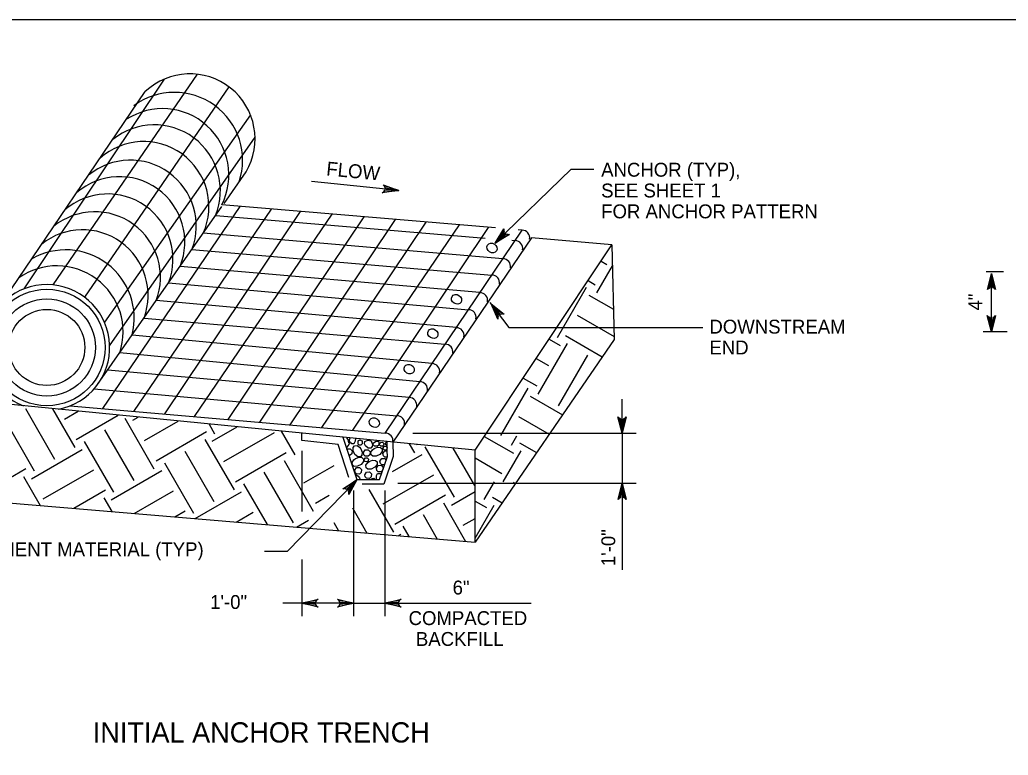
# Model space of a CAD drawing. Extents: x 636462 to 638208, y 299350 to 300538.
# Drawn here: x 636572.1 to 636785.5, y 299770.7 to 299929.4 of the extents above; entities that cross this region are included whole.
import ezdxf

# ---------------------------------------------------------------- set-up
doc = ezdxf.new("R2010")
doc.units = 0
doc.layers.add('1', color=7, linetype='Continuous')
doc.layers.add('Default', color=7, linetype='Continuous')

msp = doc.modelspace()

# ---------------------------------------------------------------- linework, layer by layer
at = {"layer": '1'}
for points in [[(637287.91, 299365.45), (637287.91, 299929.45), (636501.91, 299929.45), (636501.91, 299365.45), (637287.91, 299365.45), (637287.91, 299391.81), (637087.91, 299391.81), (637087.91, 299456.49), (637287.91, 299456.49), (637287.91, 299485.45), (637087.91, 299485.45), (637087.91, 299365.45), (637166.72, 299365.45), (637166.72, 299391.81), (637166.72, 299365.45), (637243.72, 299365.45), (637243.72, 299391.81), (637243.72, 299379.49), (637287.91, 299379.49)], [(636643.12, 299838.14), (636642.92, 299838.83), (636642.68, 299839.2)], [(636643.56, 299838.1), (636643.14, 299838.52), (636643.39, 299839.15)], [(636644.32, 299838.07), (636644.52, 299838.51), (636644.6, 299839.06)], [(636645.09, 299838.02), (636645.09, 299838.51), (636645.41, 299838.73), (636646, 299838.57), (636645.95, 299837.88)], [(636646.45, 299837.87), (636646.54, 299838.42), (636647.23, 299838.69), (636647.91, 299838.54), (636648.2, 299837.73)], [(636648.37, 299837.73), (636648.4, 299838.14), (636649.01, 299838.46), (636649.55, 299838.41), (636649.56, 299837.65)], [(636651.32, 299837.54), (636650.92, 299837.82), (636651.24, 299838.39)]]:
    msp.add_lwpolyline(points, dxfattribs=at)
at = {"layer": 'Default'}
for p, q in [((636573.01, 299871.38), (636603.28, 299916.64)), ((636610.34, 299917.69), (636579.2, 299872.22)), ((636565.66, 299864.62), (636599.16, 299913.93)), ((636586.08, 299869.54), (636617.24, 299914.97)), ((636621.87, 299908.92), (636590.32, 299864.17)), ((636591.46, 299859.08), (636622.86, 299904.07)), ((636674.6, 299881.18), (636691.11, 299897.18)), ((636691.11, 299897.18), (636696.01, 299897.18)), ((636616.15, 299889.76), (636620.94, 299896.61)), ((636588.84, 299850.67), (636615.69, 299889.11)), ((636619.6, 299889.16), (636589.91, 299845.49)), ((636596.71, 299844.9), (636626.4, 299888.58)), ((636674.8, 299884.5), (636615.65, 299889.49)), ((636632.56, 299888.06), (636603.31, 299844.33)), ((636609.77, 299843.77), (636639.48, 299887.48)), ((636614.35, 299887.18), (636672.52, 299882.31)), ((636646.35, 299886.9), (636616.96, 299843.15)), ((636623.88, 299842.55), (636653.15, 299886.32)), ((636659.73, 299885.77), (636630.34, 299842)), ((636637.28, 299841.4), (636667, 299885.15)), ((636673.16, 299884.63), (636643.86, 299840.83)), ((636650.96, 299840.21), (636680.51, 299884.01)), ((636680.51, 299884.01), (636679.68, 299884.08)), ((636676.35, 299877.85), (636611.68, 299883.36)), ((636682.57, 299882.35), (636652.59, 299838.25)), ((636678.28, 299881.83), (636678.99, 299881.77)), ((636699.89, 299880.82), (636682.57, 299882.35)), ((636609.23, 299879.86), (636673.97, 299874.33)), ((636671.41, 299870.53), (636606.65, 299876.17)), ((636696.61, 299870.48), (636700, 299876.35)), ((636697.55, 299877.33), (636698.8, 299876.61)), ((636784.44, 299875.01), (636780.69, 299875.01)), ((636604.18, 299872.62), (636668.92, 299866.84)), ((636688.12, 299860.82), (636694.43, 299871.74)), ((636694.75, 299873.12), (636696.27, 299872.24)), ((636694.89, 299870.02), (636700.23, 299866.94)), ((636666.32, 299862.98), (636601.51, 299868.8)), ((636673.55, 299868.43), (636677.68, 299863.01)), ((636598.88, 299865.04), (636663.9, 299859.4)), ((636692.37, 299865.65), (636700.38, 299861.03)), ((636677.68, 299863.01), (636719.56, 299863.01)), ((636661.07, 299855.2), (636596.33, 299861.38)), ((636686.34, 299860.51), (636688.71, 299859.14)), ((636689.85, 299861.28), (636697.81, 299856.68)), ((636785.26, 299862.1), (636780.03, 299862.1)), ((636684, 299848.64), (636690.31, 299859.56)), ((636658.43, 299851.29), (636593.65, 299857.56)), ((636683.54, 299856.3), (636686.19, 299854.77)), ((636688.37, 299846.12), (636694.67, 299857.04)), ((636656.13, 299847.87), (636591.04, 299853.82)), ((636680.74, 299852.1), (636683.67, 299850.4)), ((636588.11, 299849.75), (636653.49, 299843.96)), ((636675.91, 299839.67), (636681.82, 299849.91)), ((636682.28, 299848.18), (636689.23, 299844.17)), ((636573.26, 299845.49), (636579.56, 299834.58)), ((636579.1, 299845.46), (636583.93, 299837.1)), ((636582.93, 299846.09), (636650.96, 299840.21)), ((636581.74, 299843.22), (636584.69, 299844.92)), ((636584.26, 299838.85), (636593.31, 299844.07)), ((636594.72, 299843.43), (636601.03, 299832.51)), ((636596.44, 299842.97), (636597.62, 299843.65)), ((636679.76, 299843.81), (636686.37, 299840)), ((636568.89, 299842.97), (636575.19, 299832.05)), ((636598.97, 299838.6), (636606.24, 299842.8)), ((636612.93, 299842.14), (636614.13, 299840.08)), ((636613.62, 299838.43), (636619.02, 299841.55)), ((636590.35, 299840.91), (636596.66, 299829.99)), ((636601.49, 299834.24), (636612.4, 299840.54)), ((636616.14, 299834.06), (636627.06, 299840.37)), ((636628.48, 299840.62), (636631.43, 299835.51)), ((636632.96, 299838.63), (636632.94, 299840.18)), ((636641.8, 299839.31), (636644.85, 299830.17)), ((636656.92, 299840.21), (636705.14, 299840.21)), ((636672.34, 299839.5), (636678.67, 299835.85)), ((636678.21, 299837.57), (636679.4, 299839.63)), ((636585.99, 299838.39), (636592.29, 299827.47)), ((636612.03, 299838.86), (636618.33, 299827.94)), ((636640.81, 299837.71), (636632.96, 299838.63)), ((636643.08, 299830.64), (636640.81, 299837.71)), ((636651.41, 299836.41), (636651.35, 299838.34)), ((636652.59, 299838.25), (636652.69, 299835.14)), ((636656.15, 299837.9), (636657.26, 299835.97)), ((636657.72, 299837.69), (636657.81, 299837.74)), ((636659.53, 299837.27), (636665.83, 299826.35)), ((636665.52, 299836.98), (636670.2, 299828.88)), ((636679.98, 299838.11), (636683.63, 299836.01)), ((636574.61, 299830.36), (636585.52, 299836.66)), ((636607.66, 299836.34), (636613.96, 299825.42)), ((636618.66, 299829.69), (636629.58, 299836)), ((636632.96, 299836.35), (636632.96, 299823.3)), ((636649.71, 299830.17), (636651.44, 299835.15)), ((636652.69, 299835.14), (636650.68, 299829.15)), ((636651.44, 299835.15), (636651.41, 299836.4)), ((636652.55, 299831.89), (636658.94, 299835.58)), ((636670.34, 299834.83), (636676.15, 299831.48)), ((636676.45, 299829.65), (636680.32, 299836.35)), ((636603.29, 299833.82), (636609.59, 299822.9)), ((636629.12, 299834.28), (636635.43, 299823.36)), ((636633.37, 299829.45), (636639.92, 299833.23)), ((636562.43, 299826.24), (636573.35, 299832.54)), ((636572.89, 299830.82), (636576.49, 299824.58)), ((636577.13, 299826), (636588.05, 299832.3)), ((636591.78, 299825.82), (636602.7, 299832.13)), ((636624.75, 299831.75), (636631.06, 299820.84)), ((636650.54, 299824.91), (636661.46, 299831.21)), ((636620.39, 299829.23), (636625.47, 299820.44)), ((636644.88, 299830.1), (636629.76, 299814.62)), ((636644.85, 299830.17), (636649.71, 299830.17)), ((636650.68, 299829.15), (636645.99, 299829.2)), ((636653.7, 299829.39), (636705.14, 299829.39)), ((636672.34, 299825.84), (636674.55, 299829.66)), ((636678.55, 299829.64), (636679.06, 299829.35)), ((636583.7, 299823.97), (636590.57, 299827.93)), ((636590.19, 299826.26), (636591.91, 299823.27)), ((636596.75, 299822.86), (636605.23, 299827.76)), ((636609.95, 299821.75), (636619.93, 299827.51)), ((636635.89, 299825.08), (636638.85, 299826.79)), ((636644.14, 299827.78), (636644.14, 299800.69)), ((636647.41, 299828.01), (636652.73, 299818.79)), ((636650.85, 299827.78), (636650.85, 299800.69)), ((636653.06, 299820.54), (636663.98, 299826.85)), ((636665.24, 299824.66), (636670.34, 299827.61)), ((636674.11, 299826.38), (636676.2, 299825.17)), ((636663.52, 299825.12), (636668.32, 299816.82)), ((636670.34, 299825.53), (636672.81, 299824.11)), ((636670.34, 299817.51), (636674.45, 299824.62)), ((636605.55, 299822.12), (636607.75, 299823.39)), ((636618.74, 299821.01), (636622.45, 299823.14)), ((636643.86, 299824.06), (636647.01, 299818.62)), ((636659.16, 299822.6), (636662.2, 299817.33)), ((636631.79, 299819.9), (636634.36, 299821.39)), ((636639.88, 299820.88), (636640.88, 299819.14)), ((636654.79, 299820.08), (636656.07, 299817.85)), ((636667.77, 299820.3), (636670.34, 299821.79)), ((636653.78, 299818.05), (636654.33, 299818.36)), ((636629.76, 299814.62), (636624.86, 299814.62)), ((636632.96, 299812.95), (636632.96, 299800.69))]:
    msp.add_line(p, q, dxfattribs=at)
for points in [[(636653.87, 299892.62), (636635.01, 299894.52)], [(636650.72, 299893.59), (636650.48, 299893.84), (636653.87, 299892.62), (636650.72, 299893.59), (636650.88, 299893.2), (636653.87, 299892.62), (636650.83, 299892.68), (636650.61, 299892.32), (636653.87, 299892.62), (636650.3, 299892.1), (636650.61, 299892.32)], [(636677.47, 299883.06), (636677.82, 299883.09), (636674.72, 299881.25), (636677.47, 299883.06), (636677.07, 299883.19), (636674.72, 299881.25), (636676.7, 299883.56), (636676.56, 299883.96), (636674.72, 299881.25), (636676.59, 299884.33), (636676.56, 299883.96)], [(636670.34, 299836.51), (636699.89, 299880.82), (636700.4, 299860.45), (636670.34, 299816.65)], [(636781.21, 299871.46), (636780.98, 299871.19), (636781.84, 299874.7), (636781.21, 299871.46), (636781.58, 299871.66), (636781.84, 299874.7), (636782.1, 299871.67), (636782.48, 299871.48), (636781.84, 299874.7), (636782.73, 299871.2), (636782.48, 299871.48)], [(636781.84, 299862.1), (636781.84, 299874.7)], [(636675.26, 299865.15), (636675.25, 299864.8), (636673.8, 299868.1), (636675.26, 299865.15), (636675.44, 299865.53), (636673.8, 299868.1), (636675.85, 299865.86), (636676.26, 299865.94), (636673.8, 299868.1), (636676.63, 299865.87), (636676.26, 299865.94)], [(636782.48, 299865.33), (636782.7, 299865.6), (636781.84, 299862.1), (636782.48, 299865.33), (636782.11, 299865.14), (636781.84, 299862.1), (636781.58, 299865.13), (636781.21, 299865.31), (636781.84, 299862.1), (636780.95, 299865.6), (636781.21, 299865.31)], [(636702.1, 299840.21), (636702.1, 299847.54)], [(636702.73, 299843.45), (636702.96, 299843.72), (636702.1, 299840.21), (636702.73, 299843.45), (636702.36, 299843.25), (636702.1, 299840.21), (636701.84, 299843.24), (636701.46, 299843.43), (636702.1, 299840.21), (636701.21, 299843.71), (636701.46, 299843.43)], [(636702.1, 299840.21), (636702.1, 299810.69)], [(636643.14, 299838.12), (636643.13, 299837.76), (636642.64, 299837.14), (636642.54, 299837.09)], [(636644.3, 299838.03), (636644.12, 299837.89), (636643.75, 299837.91), (636643.57, 299838.08), (636643.57, 299838.09)], [(636645.68, 299836.84), (636645.97, 299836.1), (636645.91, 299835.41), (636645.6, 299835.09), (636645.05, 299835.1), (636644.42, 299835.59), (636644.04, 299836.35), (636644.03, 299837.07), (636644.31, 299837.47), (636644.89, 299837.51), (636645.4, 299837.19), (636645.7, 299836.81)], [(636645.93, 299837.9), (636645.92, 299837.8), (636645.69, 299837.61), (636645.31, 299837.63), (636645.13, 299837.81), (636645.1, 299837.97)], [(636648.2, 299837.72), (636648.16, 299837.29), (636647.85, 299836.96), (636647.3, 299836.97), (636646.67, 299837.47), (636646.47, 299837.86)], [(636648.54, 299836.88), (636649.28, 299837.17), (636649.96, 299837.11), (636650.29, 299836.8), (636650.28, 299836.25), (636649.78, 299835.62), (636649.02, 299835.24), (636648.31, 299835.23), (636647.9, 299835.52), (636647.87, 299836.09), (636648.19, 299836.6), (636648.57, 299836.9)], [(636649.57, 299837.61), (636649.28, 299837.37), (636648.65, 299837.41), (636648.36, 299837.7), (636648.35, 299837.71)], [(636649.74, 299837.87), (636649.98, 299838.21), (636650.36, 299838.23), (636650.63, 299837.96), (636650.59, 299837.57), (636650.35, 299837.38), (636649.98, 299837.4), (636649.8, 299837.57), (636649.74, 299837.87)], [(636650.49, 299837.04), (636650.73, 299837.38), (636651.11, 299837.4), (636651.37, 299837.12), (636651.33, 299836.74), (636651.1, 299836.55), (636650.72, 299836.57), (636650.55, 299836.74), (636650.49, 299837.04)], [(636642.68, 299836.68), (636642.76, 299836.8), (636643.39, 299836.84), (636643.84, 299836.38), (636643.77, 299835.74), (636643.38, 299835.41), (636643.09, 299835.43)], [(636644.5, 299834.68), (636645.24, 299834.98), (636645.92, 299834.92), (636646.25, 299834.61), (636646.24, 299834.05), (636645.75, 299833.43), (636644.99, 299833.05), (636644.27, 299833.03), (636643.87, 299833.32), (636643.83, 299833.89), (636644.15, 299834.4), (636644.53, 299834.7)], [(636646.25, 299836.01), (636646.65, 299836.57), (636647.28, 299836.61), (636647.72, 299836.15), (636647.66, 299835.51), (636647.26, 299835.19), (636646.64, 299835.23), (636646.34, 299835.52), (636646.25, 299836.01)], [(636646.43, 299834.51), (636646.67, 299834.85), (636647.05, 299834.87), (636647.31, 299834.59), (636647.27, 299834.21), (636647.04, 299834.01), (636646.66, 299834.04), (636646.49, 299834.21), (636646.43, 299834.51)], [(636650.46, 299835.8), (636650.86, 299836.36), (636651.23, 299836.38)], [(636651.39, 299834.98), (636650.85, 299835.02), (636650.56, 299835.31), (636650.46, 299835.8)], [(636644.38, 299832.19), (636644.78, 299832.76), (636645.41, 299832.79), (636645.85, 299832.34), (636645.79, 299831.7), (636645.4, 299831.37), (636644.77, 299831.42), (636644.48, 299831.7), (636644.38, 299832.19)], [(636647.46, 299834.07), (636648.2, 299834.37), (636648.88, 299834.31), (636649.21, 299834), (636649.2, 299833.45), (636648.7, 299832.82), (636647.94, 299832.44), (636647.23, 299832.42), (636646.82, 299832.71), (636646.79, 299833.28), (636647.11, 299833.79), (636647.49, 299834.09)], [(636649.06, 299832.65), (636649.46, 299833.21), (636650.09, 299833.25), (636650.54, 299832.79), (636650.5, 299832.43)], [(636650.37, 299832.07), (636650.08, 299831.83), (636649.45, 299831.87), (636649.16, 299832.16), (636649.06, 299832.65)], [(636649.81, 299834.14), (636650.21, 299834.71), (636650.84, 299834.74), (636651.18, 299834.39)], [(636650.81, 299833.32), (636650.2, 299833.37), (636649.91, 299833.65), (636649.81, 299834.14)], [(636644.49, 299831.23), (636644.6, 299831.24), (636645.11, 299830.91), (636645.41, 299830.54)], [(636645.39, 299830.57), (636645.55, 299830.17)], [(636646.52, 299831.23), (636646.91, 299831.8), (636647.55, 299831.83), (636647.99, 299831.38), (636647.93, 299830.74), (636647.53, 299830.41), (636646.91, 299830.46), (636646.61, 299830.74), (636646.52, 299831.23)], [(636649.14, 299830.17), (636649.05, 299830.35), (636649.04, 299831.06), (636649.32, 299831.47), (636649.89, 299831.51), (636650.13, 299831.36)], [(636642.16, 299828.21), (636641.81, 299828.17), (636644.83, 299830.14), (636642.16, 299828.21), (636642.57, 299828.1), (636644.83, 299830.14), (636642.95, 299827.75), (636643.1, 299827.36), (636644.83, 299830.14), (636643.1, 299826.98), (636643.1, 299827.36)], [(636647.95, 299830.17), (636648.12, 299830.41), (636648.5, 299830.44), (636648.75, 299830.17)], [(636701.46, 299826.16), (636701.24, 299825.89), (636702.1, 299829.39), (636701.46, 299826.16), (636701.83, 299826.35), (636702.1, 299829.39), (636702.36, 299826.36), (636702.73, 299826.18), (636702.1, 299829.39), (636702.98, 299825.9), (636702.73, 299826.18)], [(636644.14, 299803.48), (636628.85, 299803.48)], [(636636.19, 299802.84), (636636.46, 299802.62), (636632.96, 299803.48), (636636.19, 299802.84), (636636, 299803.21), (636632.96, 299803.48), (636635.99, 299803.74), (636636.17, 299804.11), (636632.96, 299803.48), (636636.45, 299804.36), (636636.17, 299804.11)], [(636640.9, 299804.11), (636640.64, 299804.34), (636644.14, 299803.48), (636640.9, 299804.11), (636641.1, 299803.74), (636644.14, 299803.48), (636641.11, 299803.22), (636640.92, 299802.84), (636644.14, 299803.48), (636640.64, 299802.59), (636640.92, 299802.84)], [(636644.14, 299803.48), (636658.21, 299803.48), (636682.46, 299803.48)], [(636654.11, 299802.84), (636654.38, 299802.62), (636650.88, 299803.48), (636654.11, 299802.84), (636653.91, 299803.21), (636650.88, 299803.48), (636653.91, 299803.74), (636654.09, 299804.11), (636650.88, 299803.48), (636654.37, 299804.36), (636654.09, 299804.11)]]:
    msp.add_lwpolyline(points, dxfattribs=at)
msp.add_lwpolyline([(636561.34, 299847.21), (636561.85, 299825.81), (636670.34, 299816.65), (636670.34, 299836.51)], close=True, dxfattribs=at)
for radius in [12.58, 10.49, 8.21]:
    msp.add_circle((636577.89, 299858.7), radius, dxfattribs=at)
for centre, radius, start, end in [((636608.81, 299903.72), 14.05, 329.6284, 133.3749), ((636605.48, 299899.09), 14.69, 341.4716, 126.6401), ((636602.87, 299895.94), 14.32, 333.2109, 122.7801), ((636601.1, 299892.5), 14.27, 338.0976, 128.8356), ((636598.81, 299889.08), 14.08, 335.9915, 132.0194), ((636595.93, 299884.9), 14.23, 339.2485, 129.261), ((636593.59, 299881.47), 14.1, 337.9055, 130.941), ((636591.04, 299877.74), 14.1, 338.7341, 130.9356), ((636588.27, 299873.83), 14.16, 339.1996, 128.729), ((636585.62, 299869.96), 14.14, 339.6408, 128.5959), ((636680.51, 299882.36), 1.65, 349.2187, 90.1506), ((636679, 299880.11), 1.65, 349.2187, 90.1506), ((636582, 299865), 14.77, 345.8457, 120.0582), ((636676.36, 299876.2), 1.65, 349.2187, 90.1506), ((636580.07, 299862.02), 14.3, 341.8248, 125.2022), ((636673.98, 299872.68), 1.65, 349.2187, 90.1506), ((636577.89, 299858.7), 13.58, 280.4201, 248.3708), ((636671.41, 299868.87), 1.65, 349.2187, 90.1506), ((636668.93, 299865.19), 1.65, 349.2187, 90.1506), ((636666.32, 299861.32), 1.65, 349.2187, 90.1506), ((636663.91, 299857.75), 1.65, 349.2187, 90.1506), ((636661.07, 299853.55), 1.65, 349.2187, 90.1506), ((636658.44, 299849.64), 1.65, 349.2187, 90.1506), ((636656.13, 299846.22), 1.65, 349.2187, 90.1506), ((636653.49, 299842.31), 1.65, 349.2187, 90.1506), ((636650.97, 299838.56), 1.65, 349.2187, 90.1506)]:
    msp.add_arc(centre, radius, start, end, dxfattribs=at)
for centre in [(636674.01, 299880.17), (636666.35, 299869.1), (636661.24, 299861.68), (636656.13, 299854.02), (636648.59, 299842.46)]:
    msp.add_ellipse(centre, major_axis=(0.973, -0.608), ratio=0.861411, dxfattribs=at)

# ---------------------------------------------------------------- texts
for s, rotation, p in [('FLOW', 354.4427, (636638.14, 299895.86)), ('4"', 90, (636779.86, 299866.67)), ('1\'-0"', 90, (636700.62, 299811.47))]:
    msp.add_text(s, height=2.998, rotation=rotation, dxfattribs=at).set_placement(p)
for s, height, p in [('ANCHOR (TYP),', 2.998, (636697.58, 299895.57)), ('SEE SHEET 1', 2.998, (636697.58, 299891.08)), ('FOR ANCHOR PATTERN', 2.998, (636697.58, 299886.58)), ('DOWNSTREAM', 2.998, (636720.95, 299861.69)), ('END', 2.998, (636720.95, 299857.19)), ('EMBANKMENT MATERIAL (TYP)', 2.998, (636550.73, 299813.61)), ('6"', 2.998, (636665.51, 299805.36)), ('1\'-0"', 2.998, (636613.15, 299802.24)), ('COMPACTED', 2.998, (636656, 299798.76)), ('BACKFILL', 2.998, (636657.58, 299794.26)), ('INITIAL ANCHOR TRENCH', 4.3721, (636587.82, 299773.4))]:
    msp.add_text(s, height=height, dxfattribs=at).set_placement(p)

doc.saveas('drawing.dxf')
